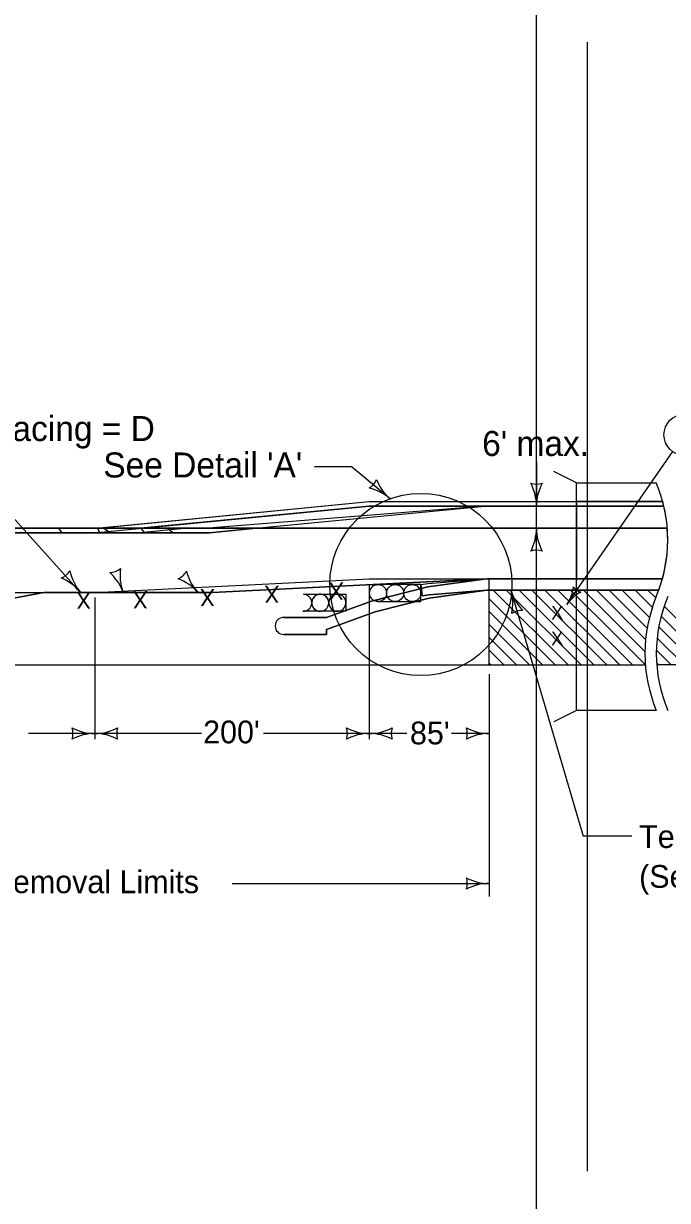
# Model space of a CAD drawing. Extents: x -2135039 to 114557, y -2139150 to -409929.
# Drawn here: x -2129338 to -2128772, y -2138203 to -2137170 of the extents above; entities that cross this region are included whole.
import ezdxf

# ---------------------------------------------------------------- set-up
doc = ezdxf.new("R2010")
doc.units = 0
for name, color, linetype in [('dsnNonPlotable', 7, 'Continuous'), ('dsnStdLabel', 7, 'Continuous'), ('dsnStdLineWork', 7, 'Continuous'), ('dsnStdNote', 7, 'Continuous'), ('dsnStdShading', 7, 'Continuous'), ('Level 2', 7, 'Continuous'), ('StdDimension', 7, 'Continuous')]:
    doc.layers.add(name, color=color, linetype=linetype)

# ---------------------------------------------------------------- blocks, each defined once
blk = doc.blocks.new('LT')
at = {"layer": 'dsnStdLabel'}
for centre, radius, start, end in [((-3.56, 0), 1.64, 342.2666, 17.7333), ((0, 4.25), 4.25, 241.9275, 270), ((0, -4.25), 4.25, 90, 118.0725)]:
    blk.add_arc(centre, radius, start, end, dxfattribs=at)

msp = doc.modelspace()

# ---------------------------------------------------------------- linework, layer by layer
at = {"layer": 'dsnNonPlotable'}
for p, q in [((-2128887.5, -2137085.9), (-2128887.5, -2138555.9)), ((-2128842.5, -2137185.9), (-2128842.5, -2138177.5))]:
    msp.add_line(p, q, dxfattribs=at)
at = {"layer": 'dsnStdLabel'}
for p, q in [((-2128928.7, -2137732.9), (-2128928.7, -2137667.2)), ((-2128925, -2137667.2), (-2128859.3, -2137732.9)), ((-2128913.7, -2137667.2), (-2128847.9, -2137732.9)), ((-2128902.4, -2137667.2), (-2128836.6, -2137732.9)), ((-2128891.1, -2137667.2), (-2128825.3, -2137732.9)), ((-2128879.7, -2137667.2), (-2128814, -2137732.9)), ((-2128868.4, -2137667.2), (-2128802.7, -2137732.9)), ((-2128857.1, -2137667.2), (-2128817.1, -2137707.1)), ((-2128845.8, -2137667.2), (-2128791.8, -2137721.2)), ((-2128834.5, -2137667.2), (-2128791.2, -2137710.5)), ((-2128823.2, -2137667.2), (-2128789.8, -2137700.5)), ((-2128811.9, -2137667.2), (-2128787.8, -2137691.2)), ((-2128800.5, -2137667.2), (-2128785.3, -2137682.4)), ((-2128789.2, -2137667.2), (-2128782.3, -2137674.1)), ((-2128928.7, -2137674.8), (-2128870.6, -2137732.9)), ((-2128775, -2137681.4), (-2128723.5, -2137732.9)), ((-2128928.7, -2137686.1), (-2128881.9, -2137732.9)), ((-2128777.6, -2137690.1), (-2128734.8, -2137732.9)), ((-2128928.7, -2137697.4), (-2128893.2, -2137732.9)), ((-2128779.6, -2137699.4), (-2128746.1, -2137732.9)), ((-2128928.7, -2137708.7), (-2128904.5, -2137732.9)), ((-2128817.1, -2137707.1), (-2128791.4, -2137732.9)), ((-2128781.1, -2137709.3), (-2128757.4, -2137732.9)), ((-2128928.7, -2137720), (-2128915.8, -2137732.9)), ((-2128781.7, -2137719.9), (-2128768.8, -2137732.9)), ((-2128928.7, -2137731.3), (-2128927.1, -2137732.9)), ((-2128817.9, -2137728.9), (-2128814, -2137732.9)), ((-2128781.5, -2137731.5), (-2128780.1, -2137732.9))]:
    msp.add_line(p, q, dxfattribs=at)
for centre, radius in [((-2128988.6, -2137662.3), 80), ((-2129026.2, -2137669.8), 7.5), ((-2129011.2, -2137669.8), 7.5), ((-2128996.2, -2137669.8), 7.5)]:
    msp.add_circle(centre, radius, dxfattribs=at)
at = {"layer": 'dsnStdLineWork'}
for p, q in [((-2128851.8, -2137572.9), (-2128871.8, -2137562.9)), ((-2129275.6, -2137616.9), (-2129034, -2137593.4)), ((-2129034, -2137593.4), (-2128775.2, -2137593.4)), ((-2128932.7, -2137593.4), (-2128775.1, -2137593.4)), ((-2129272.5, -2137612.9), (-2128949.8, -2137612.9)), ((-2128949.8, -2137612.9), (-2128772.2, -2137612.9)), ((-2129275, -2137669.2), (-2129034, -2137657.2)), ((-2129034, -2137657.2), (-2128930.7, -2137657.2)), ((-2128776.4, -2137657.2), (-2128802.7, -2137657.2)), ((-2129423.2, -2137669.2), (-2129275, -2137669.2)), ((-2128805.9, -2137667.2), (-2128779.5, -2137667.2)), ((-2128851.8, -2137772.9), (-2128871.8, -2137782.9))]:
    msp.add_line(p, q, dxfattribs=at)
for points in [[(-2128781.8, -2137772.9), (-2128851.8, -2137772.9), (-2128851.8, -2137572.9), (-2128781.8, -2137572.9)], [(-2131305.2, -2137616.9), (-2129275.6, -2137616.9)], [(-2128988.6, -2137662.3), (-2128982.6, -2137661.5), (-2128930.7, -2137657.2)], [(-2128988.6, -2137662.3), (-2128987.4, -2137672.1), (-2128987.4, -2137672.1)], [(-2128776.4, -2137657.2), (-2128930.7, -2137657.2)], [(-2128987.4, -2137672.1), (-2128981.3, -2137671.3), (-2128930.7, -2137667.2)], [(-2128930.7, -2137667.2), (-2128779.5, -2137667.2)]]:
    msp.add_lwpolyline(points, dxfattribs=at)
for centre, start, end in [((-2128901.8, -2137622.9), 337.3801, 22.6199), ((-2128661.8, -2137722.9), 157.3801, 202.6199), ((-2128651.8, -2137722.9), 157.3801, 202.6199)]:
    msp.add_arc(centre, 130, start, end, dxfattribs=at)
at = {"layer": 'dsnStdNote'}
msp.add_circle((-2128757.1, -2137530.8), 18, dxfattribs=at)
at = {"layer": 'dsnStdShading'}
for p, q in [((-2129276.8, -2137613), (-2129034, -2137589.4)), ((-2129272.5, -2137612.9), (-2129034, -2137589.4)), ((-2129034, -2137589.4), (-2128776.2, -2137589.4)), ((-2129034, -2137589.4), (-2128887.3, -2137589.4)), ((-2128886.9, -2137589.4), (-2128851.8, -2137589.4)), ((-2128851.8, -2137589.4), (-2128851.8, -2137593.4)), ((-2128851.8, -2137589.4), (-2128851.8, -2137593.4)), ((-2128802.5, -2137589.4), (-2128776.1, -2137589.4)), ((-2129034, -2137593.4), (-2129234.5, -2137612.9)), ((-2129234.5, -2137612.9), (-2129034, -2137593.4)), ((-2128932.7, -2137593.4), (-2129168.3, -2137612.3)), ((-2129133.3, -2137612.9), (-2128932.7, -2137593.4)), ((-2128887.1, -2137593.4), (-2129034, -2137593.4)), ((-2129034, -2137593.4), (-2128896.9, -2137593.4)), ((-2128896.9, -2137593.4), (-2128887.1, -2137593.4)), ((-2128879.1, -2137593.4), (-2128887.1, -2137593.4)), ((-2128887.1, -2137593.4), (-2128879.1, -2137593.4)), ((-2128851.8, -2137593.4), (-2128879.1, -2137593.4)), ((-2128879.1, -2137593.4), (-2128851.8, -2137593.4)), ((-2128775.2, -2137593.4), (-2128851.8, -2137593.4)), ((-2128851.8, -2137593.4), (-2128851.8, -2137612.9)), ((-2128851.8, -2137593.4), (-2128851.8, -2137612.9)), ((-2128851.8, -2137593.4), (-2128775.2, -2137593.4)), ((-2131301.2, -2137612.9), (-2129174.6, -2137612.9)), ((-2129272.5, -2137612.9), (-2129482.9, -2137612.9)), ((-2129479.7, -2137616.9), (-2129270.9, -2137616.9)), ((-2129270.9, -2137616.9), (-2129479.7, -2137616.9)), ((-2129303.7, -2137616.9), (-2129306.7, -2137612.9)), ((-2129306.7, -2137612.9), (-2129266.9, -2137612.9)), ((-2129261.9, -2137616.9), (-2129303.7, -2137616.9)), ((-2129270.9, -2137616.9), (-2129272.5, -2137612.9)), ((-2129234.5, -2137612.9), (-2129272.5, -2137612.9)), ((-2129211.4, -2137612.9), (-2129272.5, -2137612.9)), ((-2129272.5, -2137612.9), (-2129270.9, -2137616.9)), ((-2129270.9, -2137616.9), (-2129206.6, -2137616.9)), ((-2129231.3, -2137616.9), (-2129270.9, -2137616.9)), ((-2129266.9, -2137612.9), (-2129261.9, -2137616.9)), ((-2129261.9, -2137616.9), (-2129266.9, -2137612.9)), ((-2129266.9, -2137612.9), (-2129235.4, -2137612.9)), ((-2129234.8, -2137616.9), (-2129261.9, -2137616.9)), ((-2129235.4, -2137612.9), (-2129193.5, -2137612.9)), ((-2129234.9, -2137612.9), (-2129231.3, -2137616.9)), ((-2129193.5, -2137612.9), (-2129234.8, -2137616.9)), ((-2128949.8, -2137612.9), (-2129234.5, -2137612.9)), ((-2129206.6, -2137616.9), (-2129211.4, -2137612.9)), ((-2129168.3, -2137612.3), (-2129174.6, -2137612.9)), ((-2129174.6, -2137612.9), (-2129133.3, -2137612.9)), ((-2129174.4, -2137616.9), (-2129133.3, -2137612.9)), ((-2128949.8, -2137612.9), (-2129133.3, -2137612.9)), ((-2128897.9, -2137612.9), (-2128949.8, -2137612.9)), ((-2128887.1, -2137612.9), (-2128897.9, -2137612.9)), ((-2128887.1, -2137632.1), (-2128887.1, -2137612.9)), ((-2128851.8, -2137612.9), (-2128772.2, -2137612.9)), ((-2128772.2, -2137612.9), (-2128851.8, -2137612.9)), ((-2128851.8, -2137612.9), (-2128851.8, -2137657.2)), ((-2128851.8, -2137657.2), (-2128851.8, -2137612.9)), ((-2128930.7, -2137657.2), (-2129171.7, -2137669.2)), ((-2129171.7, -2137669.2), (-2128930.7, -2137657.2)), ((-2128987.4, -2137672.1), (-2128988.6, -2137662.3)), ((-2128928.7, -2137657.1), (-2128930.7, -2137657.2)), ((-2128930.7, -2137657.2), (-2128776.4, -2137657.2)), ((-2128930.7, -2137657.2), (-2128851.8, -2137657.2)), ((-2128928.7, -2137667.2), (-2128928.7, -2137657.1)), ((-2128851.8, -2137657.2), (-2128776.4, -2137657.2)), ((-2129319.9, -2137669.2), (-2129421.4, -2137688.7)), ((-2129421.4, -2137688.7), (-2129319.9, -2137669.2)), ((-2129204.5, -2137669.2), (-2129319.9, -2137669.2)), ((-2129319.9, -2137669.2), (-2129171.7, -2137669.2)), ((-2129251.1, -2137666.8), (-2129250.3, -2137668.8)), ((-2129171.7, -2137669.2), (-2129204.5, -2137669.2)), ((-2129204.3, -2137669.5), (-2129204.5, -2137669.2)), ((-2129186.4, -2137667), (-2129184.8, -2137668.8)), ((-2129184.8, -2137668.8), (-2129186.4, -2137667)), ((-2129091.6, -2137670.8), (-2129077.1, -2137670.8)), ((-2129076.6, -2137670.8), (-2129061.6, -2137670.8)), ((-2129061.6, -2137670.8), (-2129054.5, -2137670.8)), ((-2129054.5, -2137670.8), (-2129054.5, -2137678.3)), ((-2128779.5, -2137667.2), (-2128930.7, -2137667.2)), ((-2128928.7, -2137732.9), (-2128928.7, -2137667.2)), ((-2129054.5, -2137678.7), (-2129054.5, -2137685.8)), ((-2129109.1, -2137691.2), (-2129071.5, -2137691.2)), ((-2129071.5, -2137691.2), (-2129109.1, -2137691.2)), ((-2129077.4, -2137685.8), (-2129092, -2137685.8)), ((-2129062.4, -2137685.8), (-2129077.4, -2137685.8)), ((-2129054.5, -2137685.8), (-2129062.4, -2137685.8)), ((-2129071.5, -2137706.2), (-2129071.5, -2137701.8)), ((-2129071.5, -2137706.2), (-2129109.1, -2137706.2)), ((-2129109.1, -2137706.2), (-2129071.5, -2137706.2)), ((-2131301.2, -2137732.9), (-2128969, -2137732.9)), ((-2129871.5, -2137732.9), (-2129040.8, -2137732.9)), ((-2129040.8, -2137732.9), (-2128791.4, -2137732.9)), ((-2128611, -2137732.9), (-2128781.4, -2137732.9))]:
    msp.add_line(p, q, dxfattribs=at)
for points in [[(-2128776.2, -2137589.4), (-2128802.5, -2137589.4), (-2128851.8, -2137589.4)], [(-2128776.2, -2137589.4), (-2128776.2, -2137589.4)], [(-2129133.3, -2137612.9), (-2129174.6, -2137612.9), (-2129234.9, -2137612.9)], [(-2129231.3, -2137616.9), (-2129175.4, -2137616.9), (-2129174.4, -2137616.9)], [(-2129175.4, -2137616.9), (-2129179.7, -2137616.9), (-2129231.3, -2137616.9)], [(-2129133.3, -2137612.9), (-2129174.4, -2137616.9), (-2129175.4, -2137617)], [(-2129175.4, -2137617), (-2129175.4, -2137616.9)], [(-2128851.8, -2137612.9), (-2128879.1, -2137612.9), (-2128887.1, -2137612.9), (-2128897.9, -2137612.9), (-2128949.8, -2137612.9)], [(-2128851.8, -2137612.9), (-2128879.1, -2137612.9), (-2128887.1, -2137612.9)], [(-2129071.5, -2137691.2), (-2129032.1, -2137676.8), (-2128982.6, -2137664.4), (-2128930.7, -2137657.2)], [(-2128930.7, -2137657.2), (-2128982.6, -2137664.4), (-2129032.1, -2137676.8), (-2129071.5, -2137691.2)], [(-2128988.6, -2137662.3), (-2128982.6, -2137661.5), (-2128931, -2137657.2), (-2128930.7, -2137657.2)], [(-2128930.7, -2137657.2), (-2128930.7, -2137657.2)], [(-2129250.3, -2137668.8), (-2129250.3, -2137668.8), (-2129251.1, -2137666.8)], [(-2129250.3, -2137668.8), (-2129250.3, -2137668.8)], [(-2129184.8, -2137668.8), (-2129184.8, -2137668.9)], [(-2129184.8, -2137668.9), (-2129184.8, -2137668.8)], [(-2129091.6, -2137670.9), (-2129091.6, -2137670.8)], [(-2129076.6, -2137670.9), (-2129076.6, -2137670.8)], [(-2128928.7, -2137667.2), (-2128930.7, -2137667.2), (-2128981.4, -2137674.3), (-2129028.7, -2137686.2), (-2129071.5, -2137701.8)], [(-2129071.5, -2137701.8), (-2129028.7, -2137686.2), (-2128981.4, -2137674.3), (-2128930.7, -2137667.2), (-2128928.7, -2137667.2)], [(-2129061.6, -2137670.9), (-2129061.6, -2137670.8)], [(-2129061.6, -2137670.8), (-2129061.6, -2137670.9)], [(-2128930.7, -2137667.2), (-2128981.3, -2137671.3), (-2128987.4, -2137672.1)], [(-2129084.5, -2137678.7), (-2129084.5, -2137678.7)], [(-2129069.5, -2137678.7), (-2129069.5, -2137678.7)], [(-2129054.5, -2137678.7), (-2129054.5, -2137678.7)], [(-2129077.4, -2137685.8), (-2129077.4, -2137685.8)], [(-2129077.4, -2137685.8), (-2129077.4, -2137685.8)], [(-2129062.4, -2137685.8), (-2129062.4, -2137685.8)], [(-2129062.4, -2137685.8), (-2129062.4, -2137685.8)], [(-2129071.5, -2137701.8), (-2129071.5, -2137701.8), (-2129071.5, -2137706.2)], [(-2129040.8, -2137732.9), (-2128969, -2137732.9), (-2128928.7, -2137732.9)]]:
    msp.add_lwpolyline(points, dxfattribs=at)
for centre, radius, start, end in [((-2128929.6, -2137593.4), 42.5, 0, 5.4005), ((-2128844.6, -2137593.4), 42.5, 174.5995, 179.9824), ((-2128901.8, -2137622.9), 130, 13.1184, 14.9371), ((-2128929.6, -2137593.4), 42.5, 0, 0.0176), ((-2128901.8, -2137622.9), 130, 4.4117, 13.1184), ((-2128929.6, -2137612.9), 42.5, 331.9275, 0), ((-2128901.8, -2137622.9), 130, 344.7177, 4.4117), ((-2128887.1, -2137648.5), 16.4, 90, 107.7334), ((-2129262.6, -2137635.4), 16.4, 272.4117, 307.8784), ((-2129262.6, -2137635.4), 16.4, 272.4117, 307.8784), ((-2129290.2, -2137683.5), 42.5, 23.0899, 48.2175), ((-2129290.2, -2137683.5), 42.5, 23.0899, 48.2175), ((-2129210.4, -2137654.2), 42.5, 172.0726, 200.1275), ((-2129210.4, -2137654.2), 42.5, 172.0726, 200.1275), ((-2129208.6, -2137642.4), 16.4, 294.2304, 329.6971), ((-2129208.6, -2137642.4), 16.4, 294.2304, 329.6971), ((-2129153.2, -2137640.5), 42.5, 193.8912, 218.5415), ((-2129153.2, -2137640.5), 42.5, 193.8912, 218.5415), ((-2129216.4, -2137697.3), 42.5, 41.9813, 70.0362), ((-2129216.4, -2137697.3), 42.5, 41.9813, 70.0362), ((-2128901.8, -2137622.9), 130, 340.0928, 344.7177), ((-2129290.2, -2137683.5), 42.5, 20.1451, 20.1627), ((-2129169.9, -2137644.5), 42.5, 215.5389, 216.0818), ((-2129238.6, -2137694.5), 42.5, 36.0994, 36.117), ((-2129169.9, -2137644.5), 42.5, 216.0989, 216.0994), ((-2129153.2, -2137640.5), 42.5, 221.9461, 221.9637), ((-2129092, -2137678.4), 7.55, 3.3189, 86.8597), ((-2129092, -2137678.3), 7.5, 42.0293, 86.9975), ((-2129077, -2137678.3), 7.5, 267, 266.9552), ((-2129077, -2137678.3), 7.5, 90.3225, 176.9869), ((-2129077, -2137678.4), 7.55, 3.323, 86.8556), ((-2129077, -2137678.3), 7.5, 40.9459, 87.0002), ((-2129062, -2137678.3), 7.5, 86.9958, 177.0042), ((-2129062, -2137678.3), 7.5, 86.9975, 176.9187), ((-2129062, -2137678.3), 7.5, 356.9998, 87.0002), ((-2129062, -2137678.3), 7.5, 0, 86.9975), ((-2129092, -2137678.3), 7.5, 267.0001, 356.9999), ((-2129092, -2137678.3), 7.5, 270, 357.0043), ((-2129092, -2137678.4), 7.55, 3.3337, 42.1724), ((-2129077, -2137678.3), 7.5, 182.9876, 266.9583), ((-2129077, -2137678.3), 7.5, 267.0031, 357.0043), ((-2129077, -2137678.4), 7.55, 3.4004, 41.098), ((-2129062, -2137678.3), 7.5, 177.006, 266.994), ((-2129062, -2137678.3), 7.5, 182.9876, 267.0031), ((-2129062, -2137678.3), 7.51, 267.1005, 356.8995), ((-2129062, -2137678.3), 7.5, 267.0031, 357.0041), ((-2129109.1, -2137698.7), 7.5, 90, 270), ((-2129109.1, -2137698.7), 7.5, 90, 270)]:
    msp.add_arc(centre, radius, start, end, dxfattribs=at)
at = {"layer": 'Level 2'}
for p, q in [((-2128988.6, -2137662.3), (-2129026.2, -2137662.3)), ((-2128988.6, -2137677.3), (-2128988.6, -2137662.3)), ((-2129026.2, -2137677.3), (-2128988.6, -2137677.3))]:
    msp.add_line(p, q, dxfattribs=at)
for centre in [(-2129026.2, -2137669.8), (-2129026.2, -2137669.8), (-2129011.2, -2137669.8), (-2129011.2, -2137669.8), (-2128996.2, -2137669.8), (-2128996.2, -2137669.8)]:
    msp.add_circle(centre, 7.5, dxfattribs=at)
at = {"layer": 'StdDimension'}
for p, q in [((-2129288.1, -2137668.8), (-2129416.8, -2137525.8)), ((-2128860.4, -2137679.9), (-2128767.3, -2137545.6)), ((-2129082, -2137558.7), (-2129050, -2137558.7)), ((-2129015.7, -2137587), (-2129050, -2137558.7)), ((-2128887.1, -2137554.6), (-2128887.1, -2137593.4)), ((-2128896.9, -2137593.4), (-2128879.1, -2137593.4)), ((-2128897.9, -2137612.9), (-2128879.1, -2137612.9)), ((-2128887.1, -2137644.9), (-2128887.1, -2137612.9)), ((-2129034, -2137662), (-2129034, -2137798.1)), ((-2128909.6, -2137667.2), (-2128846.1, -2137883.2)), ((-2129275, -2137673.6), (-2129275, -2137798.1)), ((-2128928.7, -2137740.9), (-2128928.7, -2137936.3)), ((-2129181.2, -2137793.2), (-2129333.4, -2137793.2)), ((-2129033.9, -2137793.2), (-2129127, -2137793.2)), ((-2129000.9, -2137793.2), (-2129033.9, -2137793.2)), ((-2128928.6, -2137793.2), (-2128961.6, -2137793.2)), ((-2128803.2, -2137883.2), (-2128846.1, -2137883.2)), ((-2129154.4, -2137924.9), (-2128928.7, -2137924.9))]:
    msp.add_line(p, q, dxfattribs=at)
for centre, radius, start, end in [((-2129042.6, -2137563.6), 16.4, 301.2201, 336.6868), ((-2129043.6, -2137619.1), 42.5, 48.9535, 77.026), ((-2128987.8, -2137555), 42.5, 200.881, 228.9535), ((-2128887.1, -2137557.8), 16.4, 252.2666, 287.7334), ((-2128929.6, -2137593.4), 42.5, 0, 28.0725), ((-2128844.6, -2137593.4), 42.5, 151.9275, 180), ((-2128929.6, -2137612.9), 42.5, 331.9275, 0), ((-2128844.6, -2137612.9), 42.5, 180, 208.0725), ((-2128887.1, -2137648.5), 16.4, 72.2666, 107.7334), ((-2129310.7, -2137641.3), 16.4, 291.6303, 327.097), ((-2129255.2, -2137641.9), 42.5, 191.2912, 219.3636), ((-2129321, -2137695.8), 42.5, 39.3636, 67.4361), ((-2128950.4, -2137679.2), 42.5, 348.3144, 16.3869), ((-2128868.8, -2137655.2), 42.5, 196.3869, 224.4594), ((-2128899.6, -2137701.4), 16.4, 88.6536, 124.1203), ((-2129310.7, -2137793.2), 16.4, 342.2667, 17.7334), ((-2129275, -2137750.7), 42.5, 241.9275, 270), ((-2129275, -2137835.7), 42.5, 90, 118.0725), ((-2129275, -2137750.7), 42.5, 270, 298.0725), ((-2129275, -2137835.7), 42.5, 61.9275, 90), ((-2129239.4, -2137793.2), 16.4, 162.2666, 197.7334), ((-2129069.5, -2137793.2), 16.4, 342.2667, 17.7334), ((-2129033.9, -2137750.7), 42.5, 241.9275, 270), ((-2129033.9, -2137835.7), 42.5, 90, 118.0725), ((-2129033.9, -2137750.7), 42.5, 270, 298.0725), ((-2129033.9, -2137835.7), 42.5, 61.9275, 90), ((-2128998.3, -2137793.2), 16.4, 162.2666, 197.7334), ((-2128964.3, -2137793.2), 16.4, 342.2667, 17.7334), ((-2128928.6, -2137750.7), 42.5, 241.9275, 270), ((-2128928.6, -2137835.7), 42.5, 90, 118.0725), ((-2128964.3, -2137924.9), 16.4, 342.2667, 17.7334), ((-2128928.7, -2137882.4), 42.5, 241.9275, 270), ((-2128928.7, -2137967.4), 42.5, 90, 118.0725)]:
    msp.add_arc(centre, radius, start, end, dxfattribs=at)

# ---------------------------------------------------------------- block references
at = {"layer": 'StdDimension', "xscale": 7.999600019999, "yscale": 7.999200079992, "rotation": -124.70293665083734}
msp.add_blockref('LT', (-2128860.4, -2137679.9), dxfattribs=at)

# ---------------------------------------------------------------- texts
at = {"layer": 'dsnStdLabel'}
for p in [(-2129056.3, -2137660.5), (-2129278.1, -2137668.6), (-2129228.4, -2137668.1), (-2129169.4, -2137666.1), (-2129112.8, -2137663.3)]:
    msp.add_text('X', height=15, rotation=180, dxfattribs=at).set_placement(p)
for p in [(-2128874.2, -2137693.1), (-2128874.2, -2137715.7)]:
    msp.add_text('X', height=12, dxfattribs=at).set_placement(p)
at = {"layer": 'StdDimension'}
for s, height, p in [('Spacing = D', 22, (-2129383.4, -2137536.3)), ("6' max.", 22, (-2128934.8, -2137549.4)), ("See Detail 'A'", 22, (-2129267.6, -2137568.3)), ("200'", 20, (-2129179.9, -2137801.8)), ("85'", 20, (-2128998.2, -2137802.7)), ('Temporary Barrier Rail', 20, (-2128796.9, -2137893.7)), ('(See Typical 8210)', 20, (-2128796.9, -2137928.7)), ('Pavement Marking Removal Limits', 20, (-2129596.7, -2137933.4))]:
    msp.add_text(s, height=height, dxfattribs=at).set_placement(p)

doc.saveas('drawing.dxf')
